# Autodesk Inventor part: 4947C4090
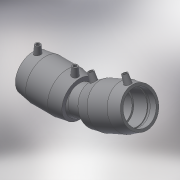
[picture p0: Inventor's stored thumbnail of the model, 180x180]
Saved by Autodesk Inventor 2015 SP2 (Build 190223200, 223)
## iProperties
Created: 2017-06
Part Number: 4947C4090
Material: Generic
Description: PLASSON ADJUSTABLE ELBOW 90
Document SubType Name: Modeling
Designer: KIM
Mass: 55.0731 g
Surface Area: 148.067 cm^2
Volume: 55.0731 cm^3
Density: 1 g/cm^3
Appearance: Default
Author: KIM
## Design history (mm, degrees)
derived "4947C4.ipt"
feature "Solid1::4947C4.ipt"
tag "TaggingFeature1"
body "Solid1"
other parameters: "d0" = 136.4, "d2" = 116, "d3" = 72, "d4" = 36, "d5" = 104.4, "d8" = 168 deg, "d10" = 28.8, "d11" = 9.6, "d29" = 77, "d30" = 15, "d31" = 54.56, "d34" = 5 deg, "d41" = 4, "d42" = 14, "d43" = 0, "d48" = 81, "d49" = 24 deg, "d50" = 341, "d51" = 78 deg, "d52" = 90 deg, "d55" = 32.2, "d57" = 168 deg, "d58" = 6.44, "d60" = 39.68667, "d62" = 3, "d63" = 0, "L_" = 341, "L_1" = 72, "D_" = 116, "A_" = 77, "d_2" = 12, "L_0" = 148, "d54" = 64.4, "d59" = 132.28891
